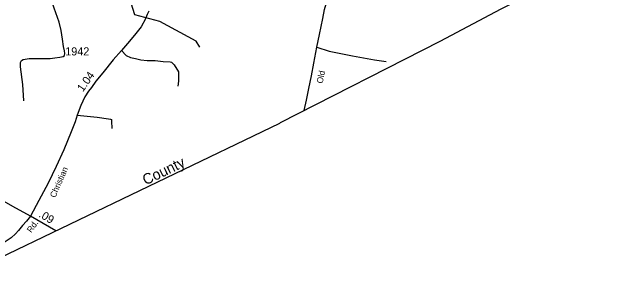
# Model space of a CAD drawing. Extents: x 2220236 to 2384410, y 720751 to 894131.
# Drawn here: x 2290003 to 2299448, y 744616 to 748897 of the extents above; entities that cross this region are included whole.
import ezdxf

# ---------------------------------------------------------------- set-up
doc = ezdxf.new("R2010")
doc.units = 0
for name, color, linetype in [('Exist Boundary Political CountyLine', 7, 'Continuous'), ('Exist Boundary Political CountyLine Label', 7, 'Continuous'), ('Exist Hydrographic Misc Water Feature', 7, 'Continuous'), ('Exist Road Non-System Type 51', 7, 'Continuous'), ('Exist Road Secondary Mileage Hundredths English Label', 7, 'Continuous'), ('Exist Road Secondary Type 51 Attributed', 7, 'Continuous'), ('Exist Road Secondary Type 51 Label', 7, 'Continuous'), ('Exist Road Secondary Type 51 Number Label', 7, 'Continuous')]:
    doc.layers.add(name, color=color, linetype=linetype)

msp = doc.modelspace()

# ---------------------------------------------------------------- linework, layer by layer
at = {"layer": 'Exist Boundary Political CountyLine'}
msp.add_lwpolyline([(2300139.9, 750264.1), (2297549.1, 748943), (2296605, 748443), (2294138.9, 747191.2), (2294128.9, 747181.3), (2290621, 745495.8), (2287877.3, 744178.1), (2270992.5, 736055.5)], dxfattribs=at)
at = {"layer": 'Exist Hydrographic Misc Water Feature'}
msp.add_lwpolyline([(2292901.2, 748359.3), (2292842.3, 748449.1), (2292281.3, 748752.5), (2291897.2, 748855.5), (2291785.2, 749221.8), (2291584.1, 749376.9), (2291483.2, 749510.2), (2291398.1, 749685.7), (2291204.1, 749916), (2291161.3, 750025.1), (2290901.3, 750237.1), (2290563.1, 750719.6), (2290401.1, 751100.1), (2290331.2, 751475.4), (2290387.2, 751733.4), (2290326.1, 752072.4), (2290490.1, 752351.1), (2290596.1, 752591.6)], dxfattribs=at)
at = {"layer": 'Exist Road Non-System Type 51'}
for points in [[(2290182.4, 747530.7), (2290166.4, 747784.2), (2290130.5, 748053.7), (2290130.5, 748123.5), (2290148.5, 748153.5), (2290170.4, 748169.4), (2290266.2, 748185.4), (2290350, 748183.4), (2290453.7, 748183.4), (2290589.4, 748185.4), (2290663.2, 748193.4), (2290737.1, 748206.1), (2290788.9, 748214.4), (2290808.8, 748227.3), (2290816.8, 748261.3), (2290810.8, 748299.2), (2290796.8, 748369.1), (2290780.9, 748480.8), (2290758.9, 748614.6), (2290729, 748742.3), (2290651.2, 748961.9), (2290461.7, 749538.8), (2290407.8, 749756.4)], [(2291690.5, 748309.2), (2291764.4, 748227.3), (2291832.2, 748197.4), (2291908, 748183.4), (2291988.8, 748163.7), (2292084.8, 748154.8), (2292210.9, 748150), (2292332.9, 748135.1), (2292442.8, 748132), (2292462.9, 748126.2), (2292505.4, 748084.7), (2292570.2, 747979.4), (2292572.9, 747921.4), (2292571.6, 747833.5), (2292560.4, 747755.3)], [(2294707.5, 748355.7), (2294900.4, 748297.2), (2295257.4, 748225.3), (2295596.6, 748162.8), (2295776.1, 748136.2)], [(2291007.3, 747309.1), (2291317.6, 747275.9), (2291487.7, 747253.6), (2291521.7, 747247.9), (2291535.8, 747240), (2291538.1, 747215.9), (2291543, 747106.1)]]:
    msp.add_lwpolyline(points, dxfattribs=at)
at = {"layer": 'Exist Road Secondary Type 51 Attributed'}
msp.add_line((2290678.7, 745523.5), (2290284.1, 745750.1), dxfattribs=at)
for points in [[(2294514.4, 747381.8), (2294546.6, 747540), (2294585.2, 747718.3), (2294623.7, 747917.9), (2294662.3, 748112.2), (2294707.5, 748355.7), (2294748.7, 748551.4), (2294800.6, 748798.9), (2294828.5, 748940), (2294869.8, 749077), (2294962.9, 749335.2), (2295019.4, 749501.6), (2295127.8, 749806.3), (2295214.2, 750044.5), (2295303.3, 750300), (2295349.9, 750422.5), (2295412.4, 750543.6), (2295485.5, 750664.7), (2295574.6, 750795.1), (2295698.3, 750968.1), (2295783.4, 751097.2), (2295838, 751183.7), (2295911.1, 751310.1)], [(2290284.1, 745750.1), (2290014.8, 745901.8), (2289703.6, 746075.4), (2288952.5, 746492.6), (2288427.9, 746792.1), (2288232.4, 746909.8), (2288014.9, 747033.6), (2287828.4, 747137.4), (2287663.8, 747233.2), (2287376.6, 747406.9), (2286816.9, 747803.4), (2286700.3, 747886), (2286321.2, 748155.5), (2285909.3, 748442.9), (2285487.7, 748742.9), (2285304, 748879.5)], [(2292112.5, 748914), (2292089.5, 748860.1), (2292061.6, 748796.2), (2291995.8, 748672.5), (2291894, 748544.7), (2291784.3, 748415), (2291690.5, 748309.2), (2291561.9, 748161.4), (2291404.3, 747961.8), (2291294.6, 747834.1), (2291226.7, 747738.3), (2291180.8, 747680.4), (2291125, 747590.5), (2291065.1, 747458.8), (2291007.3, 747309.1), (2290975.4, 747205.3), (2290911.5, 747053.6), (2290799.8, 746776.1), (2290680.1, 746516.6), (2290556.4, 746261.1), (2290414.8, 745991.6), (2290284.1, 745750.1)], [(2290284.1, 745750.1), (2290222.3, 745676.2), (2290164.4, 745606.3), (2290102.6, 745530.5), (2290054.7, 745476.6), (2289986.9, 745418.7), (2289863.2, 745332.9), (2289663.7, 745201.1), (2289398.4, 745021.5), (2289308.6, 744941.6), (2289270.7, 744897.7), (2289244.8, 744865.8), (2289216.1, 744821.1)]]:
    msp.add_lwpolyline(points, dxfattribs=at)

# ---------------------------------------------------------------- texts
at = {"layer": 'Exist Boundary Political CountyLine Label'}
msp.add_text('County', height=164.04, rotation=25.66366, dxfattribs=at).set_placement((2292063.2, 746225.1))
at = {"layer": 'Exist Road Secondary Mileage Hundredths English Label'}
for s, rotation, p in [('1.04', 54.70594, (2291094.3, 747659.4)), ('.09', 328.84484, (2290403.1, 745747.6))]:
    msp.add_text(s, height=125, rotation=rotation, dxfattribs=at).set_placement(p)
at = {"layer": 'Exist Road Secondary Type 51 Label'}
for s, rotation, p in [('Old', 78.68411, (2294796.3, 747792)), ('Christian', 66.43599, (2290667.3, 746027.3)), ('Rd.', 54.06627, (2290297.5, 745487.8))]:
    msp.add_text(s, height=95, rotation=rotation, dxfattribs=at).set_placement(p)
at = {"layer": 'Exist Road Secondary Type 51 Number Label'}
msp.add_text('1942', height=125, dxfattribs=at).set_placement((2290821.9, 748230.3))

doc.saveas('drawing.dxf')
